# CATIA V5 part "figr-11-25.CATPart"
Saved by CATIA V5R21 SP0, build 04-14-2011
Part number: Part1
Bounding box of the stored display mesh (mm): x -89.703 to 75.958, y -127.286 to 108.862, z -26.487 to 19.815
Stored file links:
  D:\CATIA V5R21 E-RESOURCES\CATIA-V5R21\catia-v5r21-prt\c11-catia-v5r21-prt\c11-catia-v5r21-figr-11-25.CATPart
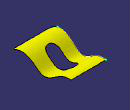
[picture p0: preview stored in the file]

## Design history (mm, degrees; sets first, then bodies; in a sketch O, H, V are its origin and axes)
Set1
  Extrude1: Element1 Sketch3, Lim1 86, Lim2 94, Direction yz-plane
  Sketch1 on xy-plane, origin (0, 0, 0), H (1, 0, 0), V (0, 1, 0)
    line L1 (64.3059, 108.8616) -> (75.9293, -106.0218)
    arc A1 centre (55.7837, -107.1115) radius 20.175 from (75.9293, -106.0218) to (55.7837, -127.2865) cw
    line L2 (55.7837, -127.2865) -> (-64.7868, -127.2865)
    arc A2 centre (-64.7868, -102.3613) radius 24.9252 from (-64.7868, -127.2865) to (-89.6873, -101.2501) cw
    line L3 (-89.6873, -101.2501) -> (-80.3115, 108.8616)
    line L4 (-80.3115, 108.8616) -> (64.3059, 108.8616)
    tangency: A1 L1, A2 L2, A2 L3, A1 L2
    horizontal: L2 H, L4 H
  Extrude2: Element1 Sketch1, Lim1 86, Lim2 94, Direction xy-plane
  Split1: ToCut Extrude1, Cutting Extrude2
  Sketch2 on xy-plane, origin (0, 0, 0), H (1, 0, 0), V (0, 1, 0)
    construction line L1 (-11.3849, 28.4134) -> (-11.3849, -36.9379)
    line L2 (12.8382, 28.4134) -> (12.8382, -36.9379)
    line L3 (-35.608, -36.9379) -> (-35.608, 28.4134)
    arc A1 centre (-11.3849, -36.9379) radius 24.2231 from (12.8382, -36.9379) to (-35.608, -36.9379) cw
    arc A2 centre (-11.3849, 28.4134) radius 24.2231 from (-35.608, 28.4134) to (12.8382, 28.4134) cw
    vertical: L1 V
    tangency: A1 L2, A2 L2, A1 L3, A2 L3
    parallelism: L1 L2
  Extrude3: Element1 Sketch2, Lim1 86, Lim2 94, Direction xy-plane
  Split2: ToCut Split1, Cutting Extrude3
  Boundary1: Boundary edge of Split2, Support Split2
Body1 (main body)
  Sketch3 on yz-plane, origin (0, 0, 0), H (0, 1, 0), V (0, 0, 1)
    spline S1 through (-130.9721, 0) (-85.5087, 19.8151) (-38.0512, 0) (0, -25.6483) (60.0541, -1.7202) (134.7951, -4.3868)
    point P1 (-130.9721, 0)
    point P2 (-38.0512, 0)
    point P3 (0, -25.6483)
    coincidence: P1 H, P2 H, P3 V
